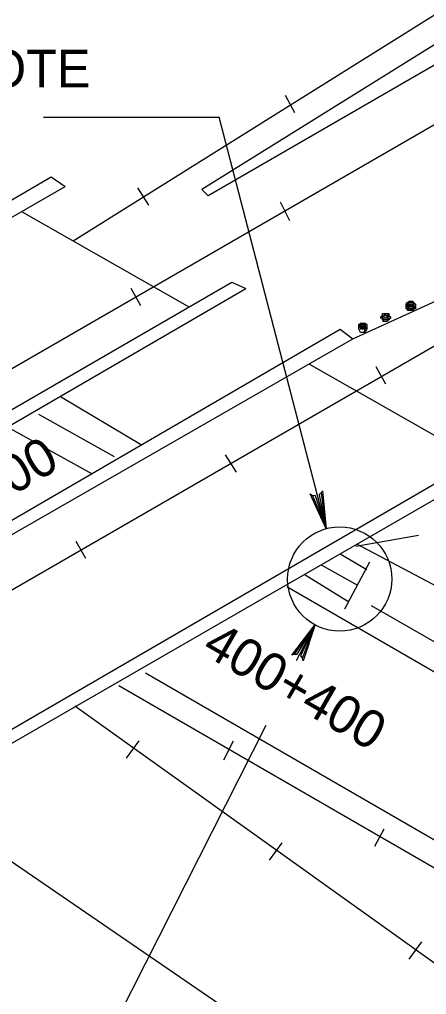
# Model space of a CAD drawing. Extents: x 36 to 2622, y -5330 to 219.
# Drawn here: x 2089.1 to 2121.5, y -4415.8 to -4338.2 of the extents above; entities that cross this region are included whole.
import ezdxf

# ---------------------------------------------------------------- set-up
doc = ezdxf.new("R2010")
doc.units = 0
doc.layers.add('2', color=7, linetype='Continuous')
doc.layers.add('3', color=7, linetype='Continuous')

# ---------------------------------------------------------------- blocks, each defined once
blk = doc.blocks.new('RARROW')
at = {"layer": '3'}
blk.add_lwpolyline([(-2.2695, 0.285), (-2.184875, 0.12075), (0, 0), (-2.2695, 0.285), (-2.38575, 0.384625), (0, 0), (-2.183125, -0.108), (-2.262875, -0.2705), (0, 0), (-2.38575, -0.379125), (-2.262875, -0.2705)], dxfattribs=at)

msp = doc.modelspace()

# ---------------------------------------------------------------- linework, layer by layer
at = {"layer": '2'}
for p, q in [((1732.847, -4161.874), (2538.009, -4712.774)), ((2239.856, -4273.83), (2104.106, -4352.205)), ((1954.606, -4443.205), (2241.981, -4277.33)), ((1962.231, -4456.455), (2237.606, -4297.455)), ((2134.106, -4330.33), (2093.356, -4355.83)), ((2135.106, -4332.08), (2103.606, -4351.705)), ((2110.231, -4344.205), (2110.981, -4345.58)), ((2090.981, -4345.955), (2104.981, -4345.955)), ((2113.481, -4378.705), (2104.981, -4345.955)), ((2043.606, -4378.58), (2091.606, -4350.705)), ((2091.606, -4350.705), (2092.731, -4351.455)), ((2044.606, -4379.08), (2092.731, -4351.455)), ((2098.481, -4351.58), (2099.356, -4352.955)), ((2103.606, -4351.705), (2104.106, -4352.205)), ((2110.606, -4354.205), (2109.856, -4352.705)), ((2089.231, -4353.455), (2102.606, -4361.08)), ((2057.981, -4386.83), (2105.981, -4359.08)), ((2059.106, -4387.455), (2107.106, -4359.58)), ((2098.731, -4360.955), (2097.981, -4359.58)), ((2105.981, -4359.08), (2107.106, -4359.58)), ((2066.606, -4390.705), (2114.606, -4362.83)), ((2114.606, -4362.83), (2115.606, -4363.58)), ((2067.481, -4391.205), (2115.606, -4363.58)), ((2112.106, -4365.58), (2125.481, -4373.205)), ((2118.231, -4367.205), (2117.481, -4365.83)), ((2098.856, -4372.08), (2092.356, -4368.205)), ((2090.606, -4369.58), (2096.606, -4372.955)), ((2088.106, -4370.58), (2094.856, -4374.33)), ((2080.856, -4399.08), (2128.856, -4371.205)), ((2081.856, -4399.58), (2129.981, -4371.83)), ((2106.356, -4374.205), (2105.481, -4372.83)), ((2094.356, -4381.08), (2093.606, -4379.705)), ((2115.856, -4380.08), (2120.856, -4379.205)), ((2114.606, -4380.705), (2116.731, -4381.955)), ((2176.481, -4412.08), (2115.981, -4379.955)), ((2114.981, -4385.08), (2116.981, -4381.33)), ((2113.106, -4381.58), (2115.981, -4383.205)), ((2111.731, -4382.33), (2115.231, -4384.455)), ((2381.856, -4540.205), (2110.356, -4383.33)), ((2382.981, -4538.33), (2117.106, -4384.83)), ((2112.606, -4386.33), (2111.106, -4389.205)), ((2376.106, -4550.08), (2099.106, -4390.205)), ((2375.106, -4551.83), (2096.981, -4391.205)), ((2131.981, -4420.33), (2093.481, -4392.83)), ((2094.606, -4422.205), (2108.731, -4394.33)), ((2097.606, -4396.955), (2098.606, -4395.58)), ((2105.356, -4397.08), (2106.106, -4395.58)), ((2117.356, -4403.955), (2118.106, -4402.58)), ((2108.981, -4405.08), (2109.981, -4403.705)), ((2120.106, -4412.955), (2121.106, -4411.58))]:
    msp.add_line(p, q, dxfattribs=at)
for points in [[(2115.606, -4363.58), (2124.981, -4359.33), (2133.606, -4355.705), (2136.981, -4353.705), (2137.981, -4352.83), (2138.981, -4351.83), (2139.981, -4350.58), (2140.481, -4349.33)], [(2120.106, -4360.955), (2120.106, -4360.955), (2120.106, -4360.955), (2120.356, -4360.83), (2120.356, -4360.955), (2120.356, -4360.955), (2120.106, -4361.08), (2120.106, -4360.955), (2119.981, -4360.955), (2120.106, -4360.83), (2120.106, -4360.83), (2120.356, -4360.83), (2120.356, -4360.955), (2120.356, -4361.08), (2120.106, -4361.08), (2120.106, -4361.08), (2119.981, -4360.955), (2119.981, -4360.83), (2120.106, -4360.705), (2120.356, -4360.705), (2120.481, -4360.83), (2120.481, -4360.955), (2120.481, -4361.08), (2120.356, -4361.205), (2120.106, -4361.205), (2120.106, -4361.205), (2119.981, -4361.08), (2119.856, -4360.955), (2119.856, -4360.83), (2119.981, -4360.705), (2120.106, -4360.705), (2120.356, -4360.705), (2120.481, -4360.83), (2120.481, -4360.955), (2120.606, -4361.08), (2120.481, -4361.205), (2120.356, -4361.205), (2120.106, -4361.33), (2119.981, -4361.205), (2119.856, -4361.205), (2119.856, -4361.08), (2119.856, -4360.955), (2119.856, -4360.83), (2119.856, -4360.83), (2119.981, -4360.705), (2119.981, -4360.705), (2120.106, -4360.58), (2120.356, -4360.58), (2120.481, -4360.705), (2120.481, -4360.705), (2120.606, -4360.83), (2120.606, -4360.83), (2120.606, -4360.955), (2120.606, -4361.08), (2120.606, -4361.205), (2120.481, -4361.205), (2120.356, -4361.33), (2120.356, -4361.33), (2120.106, -4361.33), (2119.981, -4361.33), (2119.981, -4361.205)], [(2118.231, -4361.83), (2118.231, -4361.83), (2118.231, -4361.83), (2118.231, -4361.83), (2118.356, -4361.83), (2118.356, -4361.955), (2118.231, -4361.955), (2118.106, -4361.955), (2118.106, -4361.83), (2118.106, -4361.705), (2118.231, -4361.705), (2118.356, -4361.705), (2118.356, -4361.83), (2118.356, -4361.955), (2118.231, -4361.955), (2118.106, -4361.955), (2118.106, -4361.955), (2118.106, -4361.705), (2118.106, -4361.705), (2118.356, -4361.705), (2118.356, -4361.705), (2118.481, -4361.83), (2118.481, -4361.955), (2118.356, -4362.08), (2118.231, -4362.08), (2118.106, -4362.08), (2117.981, -4361.955), (2117.981, -4361.83), (2117.981, -4361.83), (2118.106, -4361.705), (2118.231, -4361.58), (2118.356, -4361.58), (2118.481, -4361.705), (2118.481, -4361.83), (2118.481, -4361.955), (2118.481, -4362.08), (2118.356, -4362.205), (2118.231, -4362.205), (2118.106, -4362.205), (2117.981, -4362.08), (2117.981, -4361.955), (2117.856, -4361.955), (2117.856, -4361.83), (2117.981, -4361.705), (2117.981, -4361.58), (2118.106, -4361.58), (2118.231, -4361.58), (2118.356, -4361.58), (2118.356, -4361.58), (2118.481, -4361.58), (2118.481, -4361.705), (2118.606, -4361.83), (2118.606, -4361.955), (2118.606, -4361.955), (2118.481, -4362.08), (2118.481, -4362.08), (2118.356, -4362.205), (2118.231, -4362.205), (2118.231, -4362.205), (2118.106, -4362.205), (2117.981, -4362.205)], [(2116.356, -4362.58), (2116.356, -4362.58), (2116.356, -4362.58), (2116.356, -4362.58), (2116.481, -4362.58), (2116.481, -4362.705), (2116.356, -4362.705), (2116.356, -4362.705), (2116.231, -4362.58), (2116.356, -4362.58), (2116.356, -4362.455), (2116.481, -4362.455), (2116.481, -4362.58), (2116.481, -4362.705), (2116.356, -4362.83), (2116.356, -4362.705), (2116.231, -4362.705), (2116.231, -4362.455), (2116.356, -4362.455), (2116.481, -4362.455), (2116.606, -4362.455), (2116.606, -4362.58), (2116.606, -4362.705), (2116.481, -4362.83), (2116.356, -4362.83), (2116.231, -4362.83), (2116.231, -4362.705), (2116.106, -4362.58), (2116.106, -4362.58), (2116.231, -4362.455), (2116.356, -4362.33), (2116.481, -4362.33), (2116.606, -4362.455), (2116.606, -4362.58), (2116.731, -4362.705), (2116.606, -4362.83), (2116.481, -4363.08), (2116.356, -4363.08), (2116.231, -4363.08), (2116.106, -4362.83), (2116.106, -4362.705), (2116.106, -4362.705), (2116.106, -4362.58), (2116.106, -4362.455), (2116.231, -4362.33), (2116.231, -4362.33), (2116.356, -4362.33), (2116.481, -4362.33), (2116.606, -4362.33), (2116.606, -4362.33), (2116.731, -4362.455), (2116.731, -4362.58), (2116.731, -4362.705), (2116.731, -4362.705), (2116.731, -4362.83), (2116.606, -4363.08), (2116.481, -4363.08), (2116.481, -4363.08), (2116.356, -4363.08), (2116.231, -4363.08), (2116.231, -4363.08)]]:
    msp.add_lwpolyline(points, dxfattribs=at)
msp.add_circle((2114.572, -4382.703), 4.146, dxfattribs=at)

# ---------------------------------------------------------------- block references
for p, xscale, yscale, rotation in [((2113.481, -4378.704), 1.2574347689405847, 1.3092961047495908, -75.1786105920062), ((2112.606, -4386.329), 1.257434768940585, 1.3092961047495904, 62.38870025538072)]:
    msp.add_blockref('RARROW', p, dxfattribs=dict(at, xscale=xscale, yscale=yscale, rotation=rotation))

# ---------------------------------------------------------------- texts
msp.add_text('SEE NOTE', height=2.9955, dxfattribs=at).set_placement((2074.481, -4343.579))
for s, rotation, p in [('90+400', 30, (2080.731, -4380.579)), ('400+400', 329.99955, (2103.481, -4388.579))]:
    msp.add_text(s, height=3, rotation=rotation, dxfattribs=at).set_placement(p)

doc.saveas('drawing.dxf')
